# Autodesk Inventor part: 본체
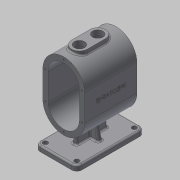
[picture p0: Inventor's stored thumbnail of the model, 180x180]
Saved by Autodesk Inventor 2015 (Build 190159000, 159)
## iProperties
Created: 2016-12
Part Number: 본체
Material: 일반
Document SubType Name: Modeling
Designer: mduedu
Density: 1 g/cm^3
Mass: 432.112 g
Surface Area: 1014.94 cm^2
Volume: 432.112 cm^3
Appearance: 기본값
Author: mduedu
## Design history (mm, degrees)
sketch "스케치1"
  geometry: L1 (40, -25)-(40, 25); L2 (-40, 25)-(-40, -25); L3 (-40, -25)-(40, 25); L4 (40, -25)-(-40, 25); L5 (0, 25)-(0, -25); A1 r 40 centre (0, 25) between (40, 25) and (-40, 25); A2 r 40 centre (0, -25) between (-40, -25) and (40, -25); 1 further point
  constraints: 10 end point, 4 point on circle, 3 tangent, 2 centre point, 2 midpoint, 2 parallel, 1 vertical
  dimensions: "d0" = 130 dimension on A2 A1; "d2" = 80 distance between parallel lines of L1 L2
extrude "돌출1" new body sketch "스케치1" stored distance "d3" = 100; taper "d4" = 0 deg
feature "쉘1" dims "d5" = 10
sketch "스케치2"
  geometry: L1 (-90, 65)-(-100, 65); L2 (-100, 65)-(-100, -65); L3 (-100, -65)-(-90, -65); L4 (-90, -65)-(-90, 65); 2 further points
  constraints: 8 end point, 2 parallel, 1 horizontal, 1 horizontal alignment, 1 midpoint, 1 perpendicular
  dimensions: "d6" = 100 distance from line of L2 point (0, 0); "d7" = 130 distance of L1.end L2.end; "d8" = 10 distance of L2.end L3.end
extrude "돌출2" join sketch "스케치2" stored distance "d9" = 80; taper "d10" = 0 deg
fillet "모깎기1" dims "d11" = 10
sketch "스케치3"
  geometry: L1 (-10, 10)-(-10, 120) reference; L2 (60, 0)-(0, 0) reference; L3 (70, 120)-(70, 10) reference; L4 (0, 130)-(60, 130) reference; A1 r 10 centre (0, 120) between (0, 130) and (-10, 120) reference; A2 r 10 centre (0, 10) between (-10, 10) and (0, 0) reference; A3 r 10 centre (60, 10) between (60, 0) and (70, 10) reference; A4 r 10 centre (60, 120) between (70, 120) and (60, 130) reference; 5 further points
  constraints: 4 coincident
hole "구멍1" sketch "스케치3" at (60, 120), (60, 10), (0, 10), (0, 120) diameter "d12" = 9; stored, may be unused: countersink angle "d16" = 90 deg, drill point angle "d18" = 118 deg; dims "d13" = 6, "d14" = 4, "d15" = 2, "d17" = 8
sketch "스케치5"
  geometry: L1 (34, 35)-(26, 35); L2 (26, 35)-(26, 95); L3 (26, 95)-(34, 95); L4 (34, 95)-(34, 35); L5 (34, 35)-(26, 95); L6 (26, 35)-(34, 95); 1 further point
  constraints: 12 end point, 2 midpoint, 2 parallel, 1 horizontal, 1 perpendicular
  dimensions: "d22" = 8 distance of L2.end L3.end; "d24" = 60 distance of L1.end L2.end
extrude "돌출3" join sketch "스케치5" stored distance "d25" = 80; taper "d26" = 0 deg
feature "면 기울기1" dims angle "d27" = 5 deg
sketch "스케치6"
  geometry: L1 (-30, -90)-(30, -90) reference; L2 (-15.072, -62.052)-(-20, -90); A1 r 40 centre (0, -25) between (-40, -25) and (40, -25) reference; 1 further point
  constraints: 2 end point, 1 point on circle, 1 point on line
  dimensions: "d28" = 20 horizontal distance of A1.centre L2.end; "d29" = 80 deg angle of L2 L1
feature "리브1" sketch "스케치6" dims "d30" = 1, "d31" = 8, "d32" = 0, "d33" = 0, "d34" = 1, "d35" = 1
fillet "모깎기2" dims "d36" = 3
fillet "모깎기3" dims "d37" = 3, "d38" = 3
node "작업 평면1"
sketch "스케치9"
  geometry: 1 further point
sketch "스케치7"
  geometry: L1 (40, 50)-(-40, 50) reference; C1 r 15 at (0, 20); 1 further point
  constraints: 1 centre point, 1 vertical alignment
  dimensions: "d40" = 30 diameter of C1; "d41" = 30 distance from line of C1.centre L1
extrude "돌출4" join sketch "스케치7" stored distance "d42" = 80; taper "d43" = 0 deg
sketch "스케치15"
  geometry: C1 r 15 at (0, -15); C2 r 15 at (0, 20) reference; 1 further point
  constraints: 1 centre point, 1 vertical alignment
  dimensions: "d83" = 30 diameter of C1; "d84" = 35 distance of C1.centre C2.centre
extrude "돌출6" join sketch "스케치15" stored distance "d85" = 10; taper "d86" = 0 deg
hole "구멍2" diameter "d46" = 20; stored, may be unused: countersink angle "d50" = 90 deg, drill point angle "d52" = 118 deg; dims "d44" = 10, "d45" = 10, "d47" = 6, "d48" = 4, "d49" = 2, "d51" = 8
hole "구멍6" diameter "d89" = 20; stored, may be unused: countersink angle "d93" = 90 deg, drill point angle "d95" = 118 deg; dims "d87" = 10, "d88" = 10, "d90" = 6, "d91" = 4, "d92" = 2, "d94" = 8
node "작업 평면2"
sketch "스케치8"
  geometry: C1 r 15 at (0, 0) reference; C2 r 15 at (0, 0); 1 further point
  constraints: 1 centre point, 1 coincident
  dimensions: "d55" = 30 diameter of C2
extrude "돌출5" cut sketch "스케치8" stored distance "d56" = 80; taper "d57" = 0 deg
sketch "스케치16"
  geometry: C1 r 15 at (0, 35); 2 further points
  constraints: 1 centre point, 1 coincident, 1 vertical alignment
  dimensions: "d96" = 30 diameter of C1
extrude "돌출7" cut sketch "스케치16" stored distance "d97" = 10; taper "d98" = 0 deg
sketch "스케치17"
  geometry: L1 (15, 0)-(15, -35); L2 (-15, 0)-(-15, -35); C1 r 10 at (0, 0) reference; C2 r 10 at (0, -35) reference; A1 r 15 centre (0, 0) between (15, 0) and (-15, 0) reference; A2 r 15 centre (0, -35) between (15, -35) and (-15, -35) reference; 1 further point
  constraints: 4 end point, 4 point on circle, 3 tangent, 1 vertical
extrude "돌출8" join sketch "스케치17" stored distance "d99" = 10; taper "d100" = 0 deg
fillet "모깎기5" dims "d101" = 3
chamfer "모따기1" distance "d58" = 1; stored, may be unused: second distance "d59" = 2, angle "d60" = 45 deg
sketch "스케치10"
  geometry: 2 further points
  constraints: 1 coincident, 1 other
feature "엠보싱1" sketch "스케치10" dims "d0" = 130, "d2" = 80, "d11" = 10, "d61" = 0.5, "d62" = 0
sketch "스케치11"
  geometry: 1 further point
hole "구멍3" sketch "스케치11" at (0, 60) diameter "d63" = 3.242; stored, may be unused: countersink angle "d67" = 90 deg, drill point angle "d69" = 120 deg; dims "d64" = 8.6, "d65" = 4, "d66" = 2, "d68" = 10.6
sketch "스케치12"
  geometry: 1 further point
hole "구멍5" sketch "스케치12" at (0, 60) diameter "d70" = 3.242; stored, may be unused: countersink angle "d74" = 90 deg, drill point angle "d76" = 120 deg; dims "d71" = 8.6, "d72" = 4, "d73" = 2, "d75" = 10.6
node "솔리드1"
mirror "대칭1"
pattern_linear "직사각형 패턴1"
pattern_linear "직사각형 패턴2"
node "투영된 루프1"
sketch "스케치13"
  geometry: L1 (-40, 25)-(-40, -25) reference; L2 (40, -25)-(40, 25) reference; L3 (35, 25)-(35, -25); L4 (-35, -25)-(-35, 25); A1 r 40 centre (0, 25) between (40, 25) and (-40, 25) reference; A2 r 40 centre (0, -25) between (-40, -25) and (40, -25) reference; A3 r 35 centre (0, 25) between (35, 25) and (-35, 25); A4 r 35 centre (0, -25) between (-35, -25) and (35, -25); 2 further points
  constraints: 5 point on circle, 4 end point, 2 centre point, 3 other
  dimensions: "d77" = 5 distance between parallel lines of L3 L2
sketch "스케치14"
  geometry: L1 (-40, 25)-(-40, -25) reference; L2 (40, -25)-(40, 25) reference; L3 (35, 25)-(35, -25); L4 (-35, -25)-(-35, 25); A1 r 40 centre (0, 25) between (40, 25) and (-40, 25) reference; A2 r 40 centre (0, -25) between (-40, -25) and (40, -25) reference; A3 r 35 centre (0, 25) between (35, 25) and (-35, 25); A4 r 35 centre (0, -25) between (-35, -25) and (35, -25); 2 further points
  constraints: 5 point on circle, 4 end point, 2 centre point, 3 other
  dimensions: "d80" = 5 distance between parallel lines of L2 L3
node "투영된 루프3"
node "투영된 루프4"
node "투영된 루프5"
